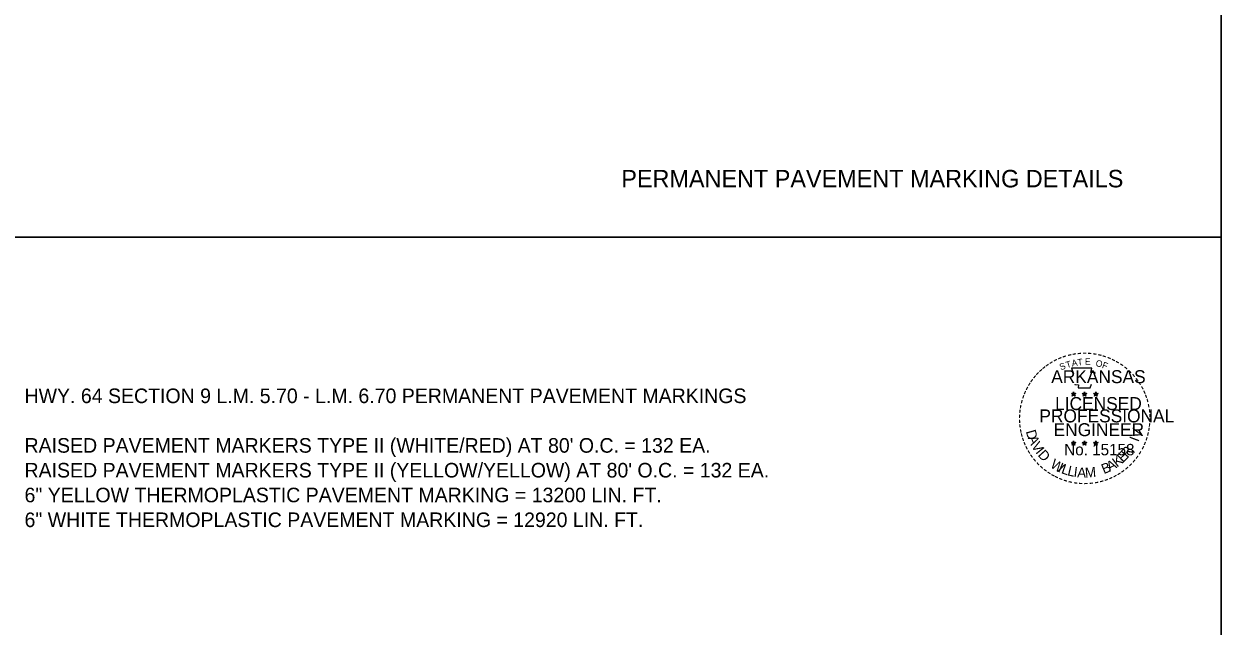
# Model space of a CAD drawing. Extents: x 1373096 to 1373266, y 381130 to 381790.
# Drawn here: x 1373173.6 to 1373266, y 381320.2 to 381366.6 of the extents above; entities that cross this region are included whole.
import ezdxf

# ---------------------------------------------------------------- set-up
doc = ezdxf.new("R2010")
doc.units = 0
for name, color, linetype in [('Default', 7, 'Continuous'), ('DSN_DRFT_Junk-No-Plot', 7, 'Continuous'), ('R_Border Notes', 7, 'Continuous'), ('R_Border PE', 7, 'Continuous')]:
    doc.layers.add(name, color=color, linetype=linetype)

msp = doc.modelspace()

# ---------------------------------------------------------------- linework, layer by layer
at = {"layer": 'Default'}
for points in [[(1373095.974, 381460.174), (1373095.974, 381350.174), (1373265.974, 381350.174), (1373265.974, 381460.174)], [(1373095.974, 381350.174), (1373095.974, 381240.174), (1373265.974, 381240.174), (1373265.974, 381350.174)]]:
    msp.add_lwpolyline(points, close=True, dxfattribs=at)
at = {"layer": 'DSN_DRFT_Junk-No-Plot'}
for points in [[(1373095.974, 381460.174), (1373265.974, 381460.174), (1373265.974, 381350.174), (1373095.974, 381350.174)], [(1373095.974, 381460.174), (1373095.974, 381350.174), (1373265.974, 381350.174), (1373265.974, 381460.174)], [(1373095.974, 381350.174), (1373265.974, 381350.174), (1373265.974, 381240.174), (1373095.974, 381240.174)], [(1373095.974, 381350.174), (1373095.974, 381240.174), (1373265.974, 381240.174), (1373265.974, 381350.174)]]:
    msp.add_lwpolyline(points, close=True, dxfattribs=at)
at = {"layer": 'R_Border PE'}
for p, q in [((1373254.429, 381338.13), (1373254.603, 381338.074)), ((1373254.429, 381338.13), (1373254.555, 381338.107)), ((1373254.429, 381338.13), (1373254.547, 381338.069)), ((1373254.495, 381337.926), (1373254.603, 381338.074)), ((1373254.495, 381337.926), (1373254.558, 381338.048)), ((1373254.495, 381337.926), (1373254.602, 381338.034)), ((1373254.603, 381338.257), (1373254.583, 381338.131)), ((1373254.71, 381337.926), (1373254.602, 381338.033)), ((1373254.603, 381338.074), (1373254.603, 381338.257)), ((1373254.603, 381338.257), (1373254.628, 381338.132)), ((1373254.777, 381338.13), (1373254.603, 381338.074)), ((1373254.71, 381337.926), (1373254.603, 381338.074)), ((1373254.777, 381338.13), (1373254.634, 381338.105)), ((1373254.71, 381337.926), (1373254.641, 381338.071)), ((1373254.777, 381338.13), (1373254.675, 381338.079)), ((1373255.264, 381338.13), (1373255.438, 381338.074)), ((1373255.264, 381338.13), (1373255.39, 381338.107)), ((1373255.264, 381338.13), (1373255.382, 381338.069)), ((1373255.33, 381337.926), (1373255.438, 381338.074)), ((1373255.33, 381337.926), (1373255.393, 381338.048)), ((1373255.33, 381337.926), (1373255.437, 381338.034)), ((1373255.438, 381338.257), (1373255.418, 381338.131)), ((1373255.545, 381337.926), (1373255.437, 381338.033)), ((1373255.438, 381338.074), (1373255.438, 381338.257)), ((1373255.438, 381338.257), (1373255.463, 381338.132)), ((1373255.612, 381338.13), (1373255.438, 381338.074)), ((1373255.545, 381337.926), (1373255.438, 381338.074)), ((1373255.612, 381338.13), (1373255.469, 381338.105)), ((1373255.545, 381337.926), (1373255.476, 381338.071)), ((1373255.612, 381338.13), (1373255.51, 381338.079)), ((1373256.146, 381338.124), (1373256.32, 381338.068)), ((1373256.146, 381338.124), (1373256.272, 381338.101)), ((1373256.146, 381338.124), (1373256.264, 381338.063)), ((1373256.212, 381337.92), (1373256.32, 381338.068)), ((1373256.212, 381337.92), (1373256.275, 381338.042)), ((1373256.212, 381337.92), (1373256.319, 381338.028)), ((1373256.32, 381338.251), (1373256.3, 381338.125)), ((1373256.427, 381337.92), (1373256.319, 381338.027)), ((1373256.32, 381338.068), (1373256.32, 381338.251)), ((1373256.32, 381338.251), (1373256.345, 381338.126)), ((1373256.494, 381338.124), (1373256.32, 381338.068)), ((1373256.427, 381337.92), (1373256.32, 381338.068)), ((1373256.494, 381338.124), (1373256.351, 381338.099)), ((1373256.427, 381337.92), (1373256.358, 381338.065)), ((1373256.494, 381338.124), (1373256.392, 381338.073)), ((1373254.427, 381334.343), (1373254.601, 381334.288)), ((1373254.427, 381334.343), (1373254.553, 381334.321)), ((1373254.427, 381334.343), (1373254.545, 381334.282)), ((1373254.493, 381334.139), (1373254.601, 381334.288)), ((1373254.493, 381334.139), (1373254.556, 381334.261)), ((1373254.493, 381334.139), (1373254.6, 381334.248)), ((1373254.601, 381334.47), (1373254.581, 381334.344)), ((1373254.708, 381334.139), (1373254.6, 381334.246)), ((1373254.601, 381334.288), (1373254.601, 381334.47)), ((1373254.601, 381334.47), (1373254.626, 381334.345)), ((1373254.775, 381334.343), (1373254.601, 381334.288)), ((1373254.708, 381334.139), (1373254.601, 381334.288)), ((1373254.775, 381334.343), (1373254.632, 381334.319)), ((1373254.708, 381334.139), (1373254.639, 381334.285)), ((1373254.775, 381334.343), (1373254.673, 381334.292)), ((1373255.261, 381334.343), (1373255.436, 381334.288)), ((1373255.261, 381334.343), (1373255.388, 381334.321)), ((1373255.261, 381334.343), (1373255.38, 381334.282)), ((1373255.328, 381334.139), (1373255.436, 381334.288)), ((1373255.328, 381334.139), (1373255.391, 381334.261)), ((1373255.328, 381334.139), (1373255.435, 381334.248)), ((1373255.436, 381334.47), (1373255.415, 381334.344)), ((1373255.542, 381334.139), (1373255.435, 381334.246)), ((1373255.436, 381334.288), (1373255.436, 381334.47)), ((1373255.436, 381334.47), (1373255.46, 381334.345)), ((1373255.609, 381334.343), (1373255.436, 381334.288)), ((1373255.542, 381334.139), (1373255.436, 381334.288)), ((1373255.609, 381334.343), (1373255.466, 381334.319)), ((1373255.542, 381334.139), (1373255.474, 381334.285)), ((1373255.609, 381334.343), (1373255.507, 381334.292)), ((1373256.145, 381334.338), (1373256.319, 381334.283)), ((1373256.145, 381334.338), (1373256.271, 381334.316)), ((1373256.145, 381334.338), (1373256.263, 381334.277)), ((1373256.211, 381334.134), (1373256.319, 381334.283)), ((1373256.211, 381334.134), (1373256.274, 381334.256)), ((1373256.211, 381334.134), (1373256.318, 381334.243)), ((1373256.319, 381334.465), (1373256.299, 381334.339)), ((1373256.426, 381334.134), (1373256.318, 381334.241)), ((1373256.319, 381334.283), (1373256.319, 381334.465)), ((1373256.319, 381334.465), (1373256.344, 381334.34)), ((1373256.493, 381334.338), (1373256.319, 381334.283)), ((1373256.426, 381334.134), (1373256.319, 381334.283)), ((1373256.493, 381334.338), (1373256.35, 381334.314)), ((1373256.426, 381334.134), (1373256.357, 381334.28)), ((1373256.493, 381334.338), (1373256.391, 381334.287))]:
    msp.add_line(p, q, dxfattribs=at)
for points in [[(1373254.449, 381340.069), (1373254.584, 381339.655)], [(1373256.205, 381339.608), (1373256.276, 381339.75), (1373255.933, 381339.738), (1373256.007, 381340.069), (1373254.449, 381340.069)], [(1373254.695, 381338.857), (1373254.695, 381338.814), (1373254.977, 381338.804), (1373254.95, 381338.568), (1373255.885, 381338.568), (1373255.985, 381338.836)], [(1373254.603, 381338.257), (1373254.71, 381337.926), (1373254.429, 381338.13), (1373254.777, 381338.13), (1373254.495, 381337.926), (1373254.603, 381338.257)], [(1373255.438, 381338.257), (1373255.545, 381337.926), (1373255.264, 381338.13), (1373255.612, 381338.13), (1373255.33, 381337.926), (1373255.438, 381338.257)], [(1373256.32, 381338.251), (1373256.427, 381337.92), (1373256.146, 381338.124), (1373256.494, 381338.124), (1373256.212, 381337.92), (1373256.32, 381338.251)], [(1373254.601, 381334.47), (1373254.708, 381334.139), (1373254.427, 381334.343), (1373254.775, 381334.343), (1373254.493, 381334.139), (1373254.601, 381334.47)], [(1373255.436, 381334.47), (1373255.542, 381334.139), (1373255.261, 381334.343), (1373255.609, 381334.343), (1373255.328, 381334.139), (1373255.436, 381334.47)], [(1373256.319, 381334.465), (1373256.426, 381334.134), (1373256.145, 381334.338), (1373256.493, 381334.338), (1373256.211, 381334.134), (1373256.319, 381334.465)]]:
    msp.add_lwpolyline(points, dxfattribs=at)
for centre, radius in [((1373254.603, 381338.074), 0.0861), ((1373254.603, 381338.074), 0.0723), ((1373254.603, 381338.074), 0.0579), ((1373254.603, 381338.074), 0.0495), ((1373254.603, 381338.074), 0.0374), ((1373254.603, 381338.074), 0.0248), ((1373254.603, 381338.074), 0.0148), ((1373255.438, 381338.074), 0.0861), ((1373255.438, 381338.074), 0.0723), ((1373255.438, 381338.074), 0.0579), ((1373255.438, 381338.074), 0.0495), ((1373255.438, 381338.074), 0.0374), ((1373255.438, 381338.074), 0.0248), ((1373255.438, 381338.074), 0.0148), ((1373256.32, 381338.068), 0.0861), ((1373256.32, 381338.068), 0.0723), ((1373256.32, 381338.068), 0.0579), ((1373256.32, 381338.068), 0.0495), ((1373256.32, 381338.068), 0.0374), ((1373256.32, 381338.068), 0.0248), ((1373256.32, 381338.068), 0.0148), ((1373254.601, 381334.287), 0.0861), ((1373254.601, 381334.287), 0.0723), ((1373254.601, 381334.287), 0.0579), ((1373254.601, 381334.287), 0.0495), ((1373254.601, 381334.287), 0.0374), ((1373254.601, 381334.287), 0.0248), ((1373254.601, 381334.287), 0.0148), ((1373255.435, 381334.287), 0.0861), ((1373255.435, 381334.287), 0.0723), ((1373255.435, 381334.287), 0.0579), ((1373255.435, 381334.287), 0.0495), ((1373255.435, 381334.287), 0.0374), ((1373255.435, 381334.287), 0.0248), ((1373255.435, 381334.287), 0.0148), ((1373256.319, 381334.282), 0.0861), ((1373256.319, 381334.282), 0.0723), ((1373256.319, 381334.282), 0.0579), ((1373256.319, 381334.282), 0.0495), ((1373256.319, 381334.282), 0.0374), ((1373256.319, 381334.282), 0.0248), ((1373256.319, 381334.282), 0.0148)]:
    msp.add_circle(centre, radius, dxfattribs=at)

# ---------------------------------------------------------------- texts
at = {"layer": 'Default'}
for s, p in [('HWY. 64 SECTION 9 L.M. 5.70 - L.M. 6.70 PERMANENT PAVEMENT MARKINGS', (1373173.695, 381337.385)), ("RAISED PAVEMENT MARKERS TYPE II (WHITE/RED) AT 80' O.C. = 132 EA.", (1373173.695, 381333.561)), ("RAISED PAVEMENT MARKERS TYPE II (YELLOW/YELLOW) AT 80' O.C. = 132 EA.", (1373173.695, 381331.649)), ('6" YELLOW THERMOPLASTIC PAVEMENT MARKING = 13200 LIN. FT.', (1373173.695, 381329.736)), ('6" WHITE THERMOPLASTIC PAVEMENT MARKING = 12920 LIN. FT.', (1373173.695, 381327.824))]:
    msp.add_text(s, height=1.125, dxfattribs=at).set_placement(p)
at = {"layer": 'R_Border Notes'}
msp.add_text('PERMANENT PAVEMENT MARKING DETAILS', height=1.35, dxfattribs=at).set_placement((1373219.719, 381354.024))
at = {"layer": 'R_Border PE'}
for s, height, rotation, p in [('-', 0.8, 10.21935, (1373254.537, 381340.834)), ('-', 0.8, 5.89682, (1373254.901, 381340.889)), ('-', 0.8, 0.18623, (1373255.287, 381340.925)), ('-', 0.8, 357.74304, (1373255.649, 381340.918)), ('-', 0.8, 352.16172, (1373256.021, 381340.89)), ('-', 0.8, 36.23174, (1373252.602, 381339.957)), ('-', 0.8, 34.06357, (1373252.891, 381340.154)), ('-', 0.8, 28.79182, (1373253.189, 381340.339)), ('-', 0.8, 24.30721, (1373253.506, 381340.498)), ('S', 0.5, 21.59401, (1373253.626, 381339.908)), ('-', 0.8, 19.17608, (1373253.823, 381340.632)), ('T', 0.5, 16.4036, (1373254.083, 381340.073)), ('-', 0.8, 13.63015, (1373254.198, 381340.753)), ('A', 0.5, 11.21318, (1373254.496, 381340.199)), ('T', 0.5, 6.02276, (1373254.921, 381340.282)), ('E', 0.5, 0.83234, (1373255.473, 381340.337)), ('O', 0.5, 350.4515, (1373256.275, 381340.232)), ('-', 0.8, 347.20489, (1373256.38, 381340.833)), ('F', 0.5, 340.07066, (1373256.752, 381340.118)), ('-', 0.8, 342.3362, (1373256.698, 381340.756)), ('-', 0.8, 337.85509, (1373257.065, 381340.644)), ('-', 0.8, 334.12109, (1373257.381, 381340.509)), ('-', 0.8, 329.64089, (1373257.67, 381340.367)), ('-', 0.8, 325.86266, (1373257.992, 381340.187)), ('-', 0.8, 50.61418, (1373251.722, 381339.077)), ('-', 0.8, 48.42305, (1373251.923, 381339.32)), ('-', 0.8, 42.96224, (1373252.147, 381339.559)), ('-', 0.8, 38.95066, (1373252.364, 381339.768)), ('-', 0.8, 320.52971, (1373258.297, 381339.974)), ('-', 0.8, 315.57859, (1373258.596, 381339.73)), ('-', 0.8, 309.87973, (1373258.881, 381339.455)), ('-', 0.8, 306.65218, (1373259.143, 381339.154)), ('-', 0.8, 62.87135, (1373251.196, 381338.223)), ('-', 0.8, 58.07063, (1373251.353, 381338.53)), ('-', 0.8, 54.23247, (1373251.515, 381338.794)), ('-', 0.7, 303.67529, (1373259.386, 381338.87)), ('-', 0.8, 299.66835, (1373259.546, 381338.566)), ('-', 0.8, 75.46096, (1373250.859, 381337.246)), ('-', 0.8, 72.39447, (1373250.957, 381337.603)), ('-', 0.8, 67.77427, (1373251.067, 381337.918)), ('-', 0.8, 294.66279, (1373259.708, 381338.26)), ('-', 0.8, 290.57283, (1373259.836, 381337.972)), ('-', 0.8, 285.12326, (1373259.953, 381337.682)), ('-', 0.8, 85.18634, (1373250.755, 381336.544)), ('-', 0.8, 81.20126, (1373250.793, 381336.889)), ('-', 0.8, 280.54934, (1373260.053, 381337.311)), ('-', 0.8, 276.59616, (1373260.134, 381336.927)), ('-', 0.8, 94.19588, (1373250.76, 381335.831)), ('-', 0.8, 89.06224, (1373250.742, 381336.193)), ('-', 0.8, 98.94793, (1373250.796, 381335.497)), ('-', 0.8, 263.5172, (1373260.172, 381335.917)), ('-', 0.8, 274.33011, (1373260.164, 381336.566)), ('-', 0.8, 269.94067, (1373260.181, 381336.25)), ('-', 0.8, 101.71495, (1373250.863, 381335.131)), ('-', 0.8, 105.45785, (1373250.944, 381334.833)), ('-', 0.8, 109.08742, (1373251.052, 381334.518)), ('D', 0.77, 286.28478, (1373250.908, 381335.2)), ('A', 0.77, 292.78351, (1373251.054, 381334.699)), ('I', 0.77, 69.03009, (1373259.593, 381334.35)), ('V', 0.77, 72.65729, (1373259.704, 381334.619)), ('-', 0.8, 252.86809, (1373259.991, 381334.891)), ('-', 0.8, 255.7626, (1373260.081, 381335.251)), ('-', 0.8, 260.99529, (1373260.136, 381335.59)), ('-', 0.8, 114.06432, (1373251.179, 381334.22)), ('-', 0.8, 115.72885, (1373251.331, 381333.911)), ('V', 0.77, 300.79357, (1373251.311, 381334.109)), ('I', 0.77, 308.35023, (1373251.627, 381333.591)), ('D', 0.77, 311.97742, (1373251.802, 381333.358)), ('R', 0.77, 50.36514, (1373258.768, 381333.105)), ('-', 0.8, 244.61971, (1373259.748, 381334.24)), ('-', 0.8, 247.88866, (1373259.879, 381334.554)), ('-', 0.8, 120.44712, (1373251.51, 381333.618)), ('-', 0.8, 125.89344, (1373251.711, 381333.337)), ('-', 0.8, 130.71812, (1373251.942, 381333.061)), ('W', 0.77, 328.07311, (1373252.741, 381332.475)), ('A', 0.77, 28.90423, (1373257.387, 381332.088)), ('K', 0.77, 36.91429, (1373257.946, 381332.407)), ('E', 0.77, 44.01755, (1373258.4, 381332.752)), (',', 0.77, 57.4684, (1373259.129, 381333.547)), ('-', 0.8, 231.25377, (1373259.135, 381333.254)), ('-', 0.8, 233.84524, (1373259.35, 381333.537)), ('-', 0.8, 239.07125, (1373259.551, 381333.864)), ('-', 0.8, 134.22381, (1373252.201, 381332.789)), ('-', 0.8, 138.93382, (1373252.463, 381332.557)), ('-', 0.8, 144.64634, (1373252.741, 381332.354)), ('-', 0.8, 148.08978, (1373253.022, 381332.168)), ('I', 0.77, 336.6877, (1373253.335, 381332.12)), ('L', 0.77, 340.3149, (1373253.6, 381331.998)), ('L', 0.77, 346.66249, (1373254.079, 381331.826)), ('I', 0.77, 353.01009, (1373254.575, 381331.707)), ('A', 0.77, 356.63729, (1373254.864, 381331.665)), ('M', 0.77, 4.64735, (1373255.506, 381331.636)), ('B', 0.77, 22.8589, (1373256.939, 381331.901)), ('-', 0.8, 212.24909, (1373258.093, 381332.288)), ('-', 0.8, 215.73633, (1373258.36, 381332.482)), ('-', 0.8, 221.08509, (1373258.635, 381332.718)), ('-', 0.8, 225.76533, (1373258.896, 381332.972)), ('-', 0.8, 151.57039, (1373253.311, 381332.006)), ('-', 0.8, 154.60019, (1373253.572, 381331.882)), ('-', 0.8, 158.56121, (1373253.884, 381331.755)), ('-', 0.8, 162.79826, (1373254.228, 381331.649)), ('-', 0.8, 167.55551, (1373254.585, 381331.567)), ('-', 0.8, 173.11546, (1373254.971, 381331.512)), ('-', 0.8, 176.51827, (1373255.345, 381331.485)), ('-', 0.8, 181.59176, (1373255.717, 381331.495)), ('-', 0.8, 185.81666, (1373256.122, 381331.533)), ('-', 0.8, 191.28576, (1373256.49, 381331.599)), ('-', 0.8, 195.47429, (1373256.854, 381331.698)), ('-', 0.8, 199.46435, (1373257.187, 381331.817)), ('-', 0.8, 204.25161, (1373257.502, 381331.956)), ('-', 0.8, 207.35684, (1373257.814, 381332.115))]:
    msp.add_text(s, height=height, rotation=rotation, dxfattribs=at).set_placement(p)
for s, height, p in [('ARKANSAS', 1, (1373252.875, 381338.925)), ('LICENSED', 1, (1373253.174, 381336.85)), ('PROFESSIONAL', 1, (1373251.962, 381335.898)), ('ENGINEER', 1, (1373253.056, 381334.836)), ('No. 15158', 0.8785, (1373253.877, 381333.36)), ('AAMU', 0.00001, (1373255.402, 381331.633))]:
    msp.add_text(s, height=height, dxfattribs=at).set_placement(p)

doc.saveas('drawing.dxf')
